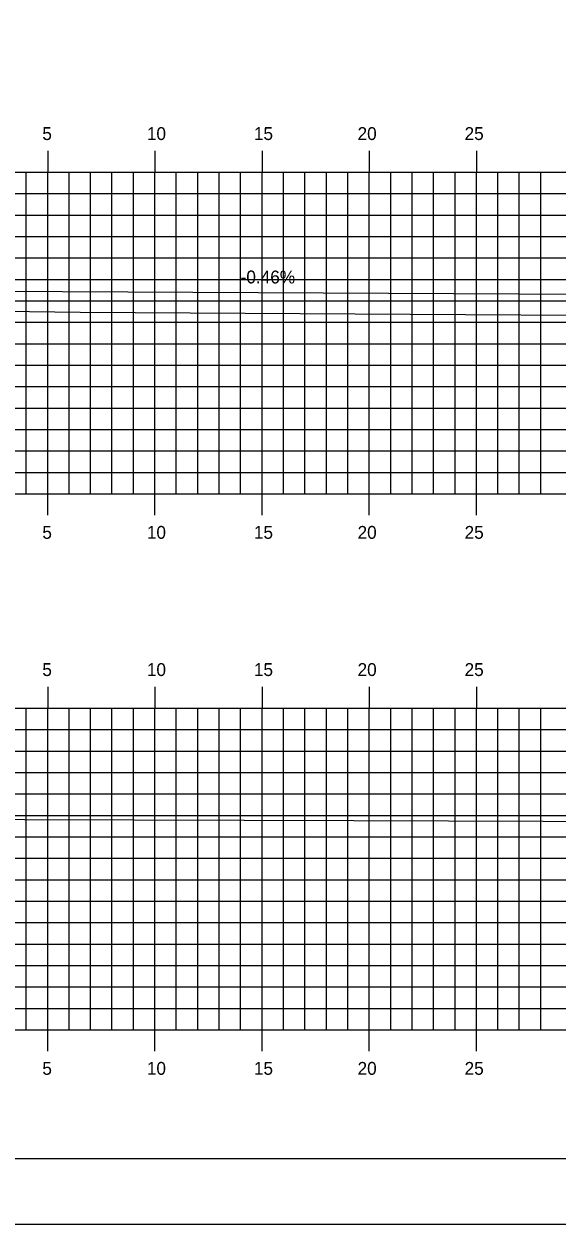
# Model space of a CAD drawing. Extents: x 1048109 to 1048279, y 781630 to 781740.
# Drawn here: x 1048195.6 to 1048220.5, y 781630.1 to 781686.1 of the extents above; entities that cross this region are included whole.
import ezdxf

# ---------------------------------------------------------------- set-up
doc = ezdxf.new("R2010")
doc.units = 0
for name, color, linetype in [('ANNOTATION', 7, 'Continuous'), ('D_Roadway_Centerline', 7, 'Continuous'), ('Default', 7, 'Continuous'), ('H_V ANNOTATION', 7, 'Continuous'), ('MAJOR', 7, 'Continuous'), ('MINOR', 7, 'Continuous'), ('S_Roadway_Centerline', 7, 'Continuous')]:
    doc.layers.add(name, color=color, linetype=linetype)

msp = doc.modelspace()

# ---------------------------------------------------------------- linework, layer by layer
at = {"layer": 'D_Roadway_Centerline'}
msp.add_line((1048191.733, 781673.663), (1048222.163, 781673.508), dxfattribs=at)
at = {"layer": 'Default'}
msp.add_line((1048116.734, 781633.195), (1048276.734, 781633.195), dxfattribs=at)
msp.add_lwpolyline([(1048108.64, 781630.136), (1048278.64, 781630.136), (1048278.64, 781740.136), (1048108.64, 781740.136)], close=True, dxfattribs=at)
at = {"layer": 'MAJOR'}
for p, q in [((1048196.733, 781680.197), (1048196.733, 781679.195)), ((1048196.733, 781680.197), (1048196.733, 781679.195)), ((1048201.733, 781680.197), (1048201.733, 781679.195)), ((1048201.733, 781680.197), (1048201.733, 781679.195)), ((1048206.733, 781680.197), (1048206.733, 781679.195)), ((1048206.733, 781680.197), (1048206.733, 781679.195)), ((1048211.733, 781680.197), (1048211.733, 781679.195)), ((1048211.733, 781680.197), (1048211.733, 781679.195)), ((1048216.733, 781680.197), (1048216.733, 781679.195)), ((1048216.733, 781680.197), (1048216.733, 781679.195)), ((1048121.733, 781679.195), (1048261.733, 781679.195)), ((1048121.733, 781679.195), (1048261.733, 781679.195)), ((1048121.733, 781679.195), (1048261.733, 781679.195)), ((1048121.733, 781679.195), (1048261.733, 781679.195)), ((1048196.733, 781664.195), (1048196.733, 781679.195)), ((1048196.733, 781664.195), (1048196.733, 781679.195)), ((1048201.733, 781664.195), (1048201.733, 781679.195)), ((1048201.733, 781664.195), (1048201.733, 781679.195)), ((1048206.733, 781664.195), (1048206.733, 781679.195)), ((1048206.733, 781664.195), (1048206.733, 781679.195)), ((1048211.733, 781664.195), (1048211.733, 781679.195)), ((1048211.733, 781664.195), (1048211.733, 781679.195)), ((1048216.733, 781664.195), (1048216.733, 781679.195)), ((1048216.733, 781664.195), (1048216.733, 781679.195)), ((1048121.733, 781674.195), (1048261.733, 781674.195)), ((1048121.733, 781674.195), (1048261.733, 781674.195)), ((1048121.733, 781669.195), (1048261.733, 781669.195)), ((1048121.733, 781669.195), (1048261.733, 781669.195)), ((1048121.733, 781664.195), (1048261.733, 781664.195)), ((1048121.733, 781664.195), (1048261.733, 781664.195)), ((1048121.733, 781664.195), (1048261.733, 781664.195)), ((1048121.733, 781664.195), (1048261.733, 781664.195)), ((1048196.733, 781663.193), (1048196.733, 781664.195)), ((1048196.733, 781663.193), (1048196.733, 781664.195)), ((1048201.733, 781663.193), (1048201.733, 781664.195)), ((1048201.733, 781663.193), (1048201.733, 781664.195)), ((1048206.733, 781663.193), (1048206.733, 781664.195)), ((1048206.733, 781663.193), (1048206.733, 781664.195)), ((1048211.733, 781663.193), (1048211.733, 781664.195)), ((1048211.733, 781663.193), (1048211.733, 781664.195)), ((1048216.733, 781663.193), (1048216.733, 781664.195)), ((1048216.733, 781663.193), (1048216.733, 781664.195)), ((1048196.733, 781655.197), (1048196.733, 781654.195)), ((1048196.733, 781655.197), (1048196.733, 781654.195)), ((1048201.733, 781655.197), (1048201.733, 781654.195)), ((1048201.733, 781655.197), (1048201.733, 781654.195)), ((1048206.733, 781655.197), (1048206.733, 781654.195)), ((1048206.733, 781655.197), (1048206.733, 781654.195)), ((1048211.733, 781655.197), (1048211.733, 781654.195)), ((1048211.733, 781655.197), (1048211.733, 781654.195)), ((1048216.733, 781655.197), (1048216.733, 781654.195)), ((1048216.733, 781655.197), (1048216.733, 781654.195)), ((1048121.733, 781654.195), (1048261.733, 781654.195)), ((1048121.733, 781654.195), (1048261.733, 781654.195)), ((1048121.733, 781654.195), (1048261.733, 781654.195)), ((1048121.733, 781654.195), (1048261.733, 781654.195)), ((1048196.733, 781639.195), (1048196.733, 781654.195)), ((1048196.733, 781639.195), (1048196.733, 781654.195)), ((1048201.733, 781639.195), (1048201.733, 781654.195)), ((1048201.733, 781639.195), (1048201.733, 781654.195)), ((1048206.733, 781639.195), (1048206.733, 781654.195)), ((1048206.733, 781639.195), (1048206.733, 781654.195)), ((1048211.733, 781639.195), (1048211.733, 781654.195)), ((1048211.733, 781639.195), (1048211.733, 781654.195)), ((1048216.733, 781639.195), (1048216.733, 781654.195)), ((1048216.733, 781639.195), (1048216.733, 781654.195)), ((1048121.733, 781649.195), (1048261.733, 781649.195)), ((1048121.733, 781649.195), (1048261.733, 781649.195)), ((1048121.733, 781644.195), (1048261.733, 781644.195)), ((1048121.733, 781644.195), (1048261.733, 781644.195)), ((1048121.733, 781639.195), (1048261.733, 781639.195)), ((1048121.733, 781639.195), (1048261.733, 781639.195)), ((1048121.733, 781639.195), (1048261.733, 781639.195)), ((1048121.733, 781639.195), (1048261.733, 781639.195)), ((1048196.733, 781638.193), (1048196.733, 781639.195)), ((1048196.733, 781638.193), (1048196.733, 781639.195)), ((1048201.733, 781638.193), (1048201.733, 781639.195)), ((1048201.733, 781638.193), (1048201.733, 781639.195)), ((1048206.733, 781638.193), (1048206.733, 781639.195)), ((1048206.733, 781638.193), (1048206.733, 781639.195)), ((1048211.733, 781638.193), (1048211.733, 781639.195)), ((1048211.733, 781638.193), (1048211.733, 781639.195)), ((1048216.733, 781638.193), (1048216.733, 781639.195)), ((1048216.733, 781638.193), (1048216.733, 781639.195))]:
    msp.add_line(p, q, dxfattribs=at)
at = {"layer": 'MINOR'}
for p, q in [((1048195.733, 781664.195), (1048195.733, 781679.195)), ((1048195.733, 781664.195), (1048195.733, 781679.195)), ((1048197.733, 781664.195), (1048197.733, 781679.195)), ((1048197.733, 781664.195), (1048197.733, 781679.195)), ((1048198.733, 781664.195), (1048198.733, 781679.195)), ((1048198.733, 781664.195), (1048198.733, 781679.195)), ((1048199.733, 781664.195), (1048199.733, 781679.195)), ((1048199.733, 781664.195), (1048199.733, 781679.195)), ((1048200.733, 781664.195), (1048200.733, 781679.195)), ((1048200.733, 781664.195), (1048200.733, 781679.195)), ((1048202.733, 781664.195), (1048202.733, 781679.195)), ((1048202.733, 781664.195), (1048202.733, 781679.195)), ((1048203.733, 781664.195), (1048203.733, 781679.195)), ((1048203.733, 781664.195), (1048203.733, 781679.195)), ((1048204.733, 781664.195), (1048204.733, 781679.195)), ((1048204.733, 781664.195), (1048204.733, 781679.195)), ((1048205.733, 781664.195), (1048205.733, 781679.195)), ((1048205.733, 781664.195), (1048205.733, 781679.195)), ((1048207.733, 781664.195), (1048207.733, 781679.195)), ((1048207.733, 781664.195), (1048207.733, 781679.195)), ((1048208.733, 781664.195), (1048208.733, 781679.195)), ((1048208.733, 781664.195), (1048208.733, 781679.195)), ((1048209.733, 781664.195), (1048209.733, 781679.195)), ((1048209.733, 781664.195), (1048209.733, 781679.195)), ((1048210.733, 781664.195), (1048210.733, 781679.195)), ((1048210.733, 781664.195), (1048210.733, 781679.195)), ((1048212.733, 781664.195), (1048212.733, 781679.195)), ((1048212.733, 781664.195), (1048212.733, 781679.195)), ((1048213.733, 781664.195), (1048213.733, 781679.195)), ((1048213.733, 781664.195), (1048213.733, 781679.195)), ((1048214.733, 781664.195), (1048214.733, 781679.195)), ((1048214.733, 781664.195), (1048214.733, 781679.195)), ((1048215.733, 781664.195), (1048215.733, 781679.195)), ((1048215.733, 781664.195), (1048215.733, 781679.195)), ((1048217.733, 781664.195), (1048217.733, 781679.195)), ((1048217.733, 781664.195), (1048217.733, 781679.195)), ((1048218.733, 781664.195), (1048218.733, 781679.195)), ((1048218.733, 781664.195), (1048218.733, 781679.195)), ((1048219.733, 781664.195), (1048219.733, 781679.195)), ((1048219.733, 781664.195), (1048219.733, 781679.195)), ((1048121.733, 781678.195), (1048261.733, 781678.195)), ((1048121.733, 781678.195), (1048261.733, 781678.195)), ((1048121.733, 781677.195), (1048261.733, 781677.195)), ((1048121.733, 781677.195), (1048261.733, 781677.195)), ((1048121.733, 781676.195), (1048261.733, 781676.195)), ((1048121.733, 781676.195), (1048261.733, 781676.195)), ((1048121.733, 781675.195), (1048261.733, 781675.195)), ((1048121.733, 781675.195), (1048261.733, 781675.195)), ((1048121.733, 781673.195), (1048261.733, 781673.195)), ((1048121.733, 781673.195), (1048261.733, 781673.195)), ((1048121.733, 781672.195), (1048261.733, 781672.195)), ((1048121.733, 781672.195), (1048261.733, 781672.195)), ((1048121.733, 781671.195), (1048261.733, 781671.195)), ((1048121.733, 781671.195), (1048261.733, 781671.195)), ((1048121.733, 781670.195), (1048261.733, 781670.195)), ((1048121.733, 781670.195), (1048261.733, 781670.195)), ((1048121.733, 781668.195), (1048261.733, 781668.195)), ((1048121.733, 781668.195), (1048261.733, 781668.195)), ((1048121.733, 781667.195), (1048261.733, 781667.195)), ((1048121.733, 781667.195), (1048261.733, 781667.195)), ((1048121.733, 781666.195), (1048261.733, 781666.195)), ((1048121.733, 781666.195), (1048261.733, 781666.195)), ((1048121.733, 781665.195), (1048261.733, 781665.195)), ((1048121.733, 781665.195), (1048261.733, 781665.195)), ((1048195.733, 781639.195), (1048195.733, 781654.195)), ((1048195.733, 781639.195), (1048195.733, 781654.195)), ((1048197.733, 781639.195), (1048197.733, 781654.195)), ((1048197.733, 781639.195), (1048197.733, 781654.195)), ((1048198.733, 781639.195), (1048198.733, 781654.195)), ((1048198.733, 781639.195), (1048198.733, 781654.195)), ((1048199.733, 781639.195), (1048199.733, 781654.195)), ((1048199.733, 781639.195), (1048199.733, 781654.195)), ((1048200.733, 781639.195), (1048200.733, 781654.195)), ((1048200.733, 781639.195), (1048200.733, 781654.195)), ((1048202.733, 781639.195), (1048202.733, 781654.195)), ((1048202.733, 781639.195), (1048202.733, 781654.195)), ((1048203.733, 781639.195), (1048203.733, 781654.195)), ((1048203.733, 781639.195), (1048203.733, 781654.195)), ((1048204.733, 781639.195), (1048204.733, 781654.195)), ((1048204.733, 781639.195), (1048204.733, 781654.195)), ((1048205.733, 781639.195), (1048205.733, 781654.195)), ((1048205.733, 781639.195), (1048205.733, 781654.195)), ((1048207.733, 781639.195), (1048207.733, 781654.195)), ((1048207.733, 781639.195), (1048207.733, 781654.195)), ((1048208.733, 781639.195), (1048208.733, 781654.195)), ((1048208.733, 781639.195), (1048208.733, 781654.195)), ((1048209.733, 781639.195), (1048209.733, 781654.195)), ((1048209.733, 781639.195), (1048209.733, 781654.195)), ((1048210.733, 781639.195), (1048210.733, 781654.195)), ((1048210.733, 781639.195), (1048210.733, 781654.195)), ((1048212.733, 781639.195), (1048212.733, 781654.195)), ((1048212.733, 781639.195), (1048212.733, 781654.195)), ((1048213.733, 781639.195), (1048213.733, 781654.195)), ((1048213.733, 781639.195), (1048213.733, 781654.195)), ((1048214.733, 781639.195), (1048214.733, 781654.195)), ((1048214.733, 781639.195), (1048214.733, 781654.195)), ((1048215.733, 781639.195), (1048215.733, 781654.195)), ((1048215.733, 781639.195), (1048215.733, 781654.195)), ((1048217.733, 781639.195), (1048217.733, 781654.195)), ((1048217.733, 781639.195), (1048217.733, 781654.195)), ((1048218.733, 781639.195), (1048218.733, 781654.195)), ((1048218.733, 781639.195), (1048218.733, 781654.195)), ((1048219.733, 781639.195), (1048219.733, 781654.195)), ((1048219.733, 781639.195), (1048219.733, 781654.195)), ((1048121.733, 781653.195), (1048261.733, 781653.195)), ((1048121.733, 781653.195), (1048261.733, 781653.195)), ((1048121.733, 781652.195), (1048261.733, 781652.195)), ((1048121.733, 781652.195), (1048261.733, 781652.195)), ((1048121.733, 781651.195), (1048261.733, 781651.195)), ((1048121.733, 781651.195), (1048261.733, 781651.195)), ((1048121.733, 781650.195), (1048261.733, 781650.195)), ((1048121.733, 781650.195), (1048261.733, 781650.195)), ((1048121.733, 781648.195), (1048261.733, 781648.195)), ((1048121.733, 781648.195), (1048261.733, 781648.195)), ((1048121.733, 781647.195), (1048261.733, 781647.195)), ((1048121.733, 781647.195), (1048261.733, 781647.195)), ((1048121.733, 781646.195), (1048261.733, 781646.195)), ((1048121.733, 781646.195), (1048261.733, 781646.195)), ((1048121.733, 781645.195), (1048261.733, 781645.195)), ((1048121.733, 781645.195), (1048261.733, 781645.195)), ((1048121.733, 781643.195), (1048261.733, 781643.195)), ((1048121.733, 781643.195), (1048261.733, 781643.195)), ((1048121.733, 781642.195), (1048261.733, 781642.195)), ((1048121.733, 781642.195), (1048261.733, 781642.195)), ((1048121.733, 781641.195), (1048261.733, 781641.195)), ((1048121.733, 781641.195), (1048261.733, 781641.195)), ((1048121.733, 781640.195), (1048261.733, 781640.195)), ((1048121.733, 781640.195), (1048261.733, 781640.195))]:
    msp.add_line(p, q, dxfattribs=at)
at = {"layer": 'S_Roadway_Centerline'}
for points in [[(1048121.733, 781673.54), (1048124.021, 781673.514), (1048124.187, 781673.511), (1048124.678, 781673.501), (1048139.044, 781673.199), (1048143.343, 781673.047), (1048145.238, 781672.981), (1048146.562, 781672.932), (1048147.063, 781672.911), (1048147.593, 781672.904), (1048149.373, 781672.876), (1048151.33, 781672.839), (1048151.337, 781672.841), (1048165.263, 781672.839), (1048171.317, 781672.812), (1048173.701, 781672.801), (1048175.841, 781672.789), (1048179.234, 781672.771), (1048191.754, 781672.77), (1048192.331, 781672.75), (1048198.246, 781672.663), (1048213.646, 781672.566), (1048223.979, 781672.514)], [(1048121.733, 781648.883), (1048132.166, 781648.791), (1048158.795, 781649.038), (1048158.833, 781649.037), (1048162.032, 781649.025), (1048164.242, 781649.039), (1048164.257, 781649.038), (1048178.681, 781649.019), (1048190.522, 781649.013), (1048211.019, 781648.954), (1048233.093, 781648.88), (1048259.004, 781648.594), (1048261.733, 781648.51)]]:
    msp.add_lwpolyline(points, dxfattribs=at)

# ---------------------------------------------------------------- texts
at = {"layer": 'ANNOTATION'}
msp.add_text('-0.46%', height=0.6, rotation=359.8096, dxfattribs=at).set_placement((1048205.731, 781674.01))
at = {"layer": 'H_V ANNOTATION'}
for s, p in [('5', (1048196.484, 781680.695)), ('10', (1048201.359, 781680.695)), ('15', (1048206.351, 781680.695)), ('20', (1048211.187, 781680.695)), ('25', (1048216.179, 781680.695)), ('5', (1048196.484, 781662.095)), ('10', (1048201.359, 781662.095)), ('15', (1048206.351, 781662.095)), ('20', (1048211.187, 781662.095)), ('25', (1048216.179, 781662.095)), ('5', (1048196.484, 781655.695)), ('10', (1048201.359, 781655.695)), ('15', (1048206.351, 781655.695)), ('20', (1048211.187, 781655.695)), ('25', (1048216.179, 781655.695)), ('5', (1048196.484, 781637.095)), ('10', (1048201.359, 781637.095)), ('15', (1048206.351, 781637.095)), ('20', (1048211.187, 781637.095)), ('25', (1048216.179, 781637.095))]:
    msp.add_text(s, height=0.6, dxfattribs=at).set_placement(p)

doc.saveas('drawing.dxf')
